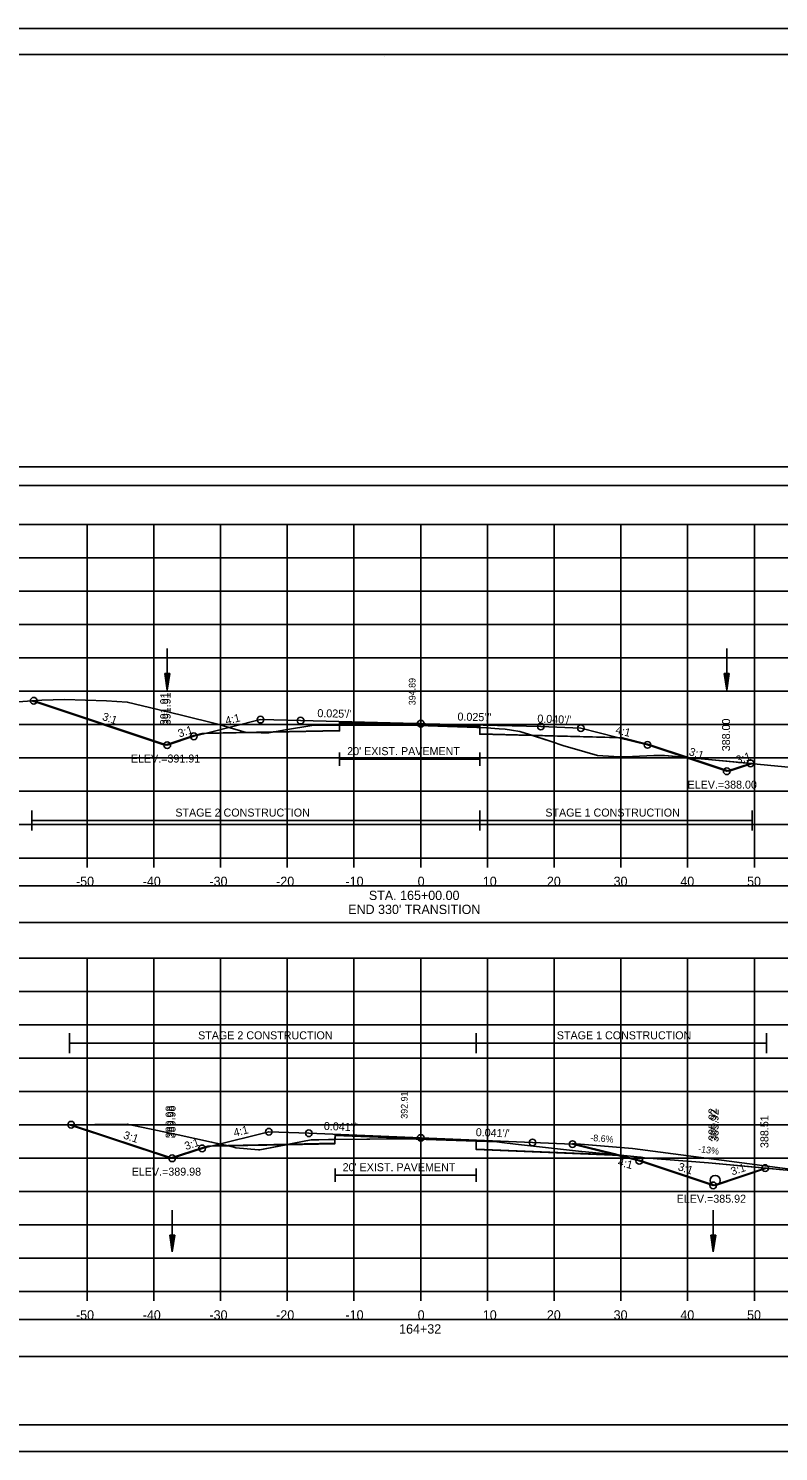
# Model space of a CAD drawing. Extents: x 1376273 to 1384221, y 378927 to 384592.
# Drawn here: x 1378165.7 to 1378278.1, y 380538.5 to 380751.8 of the extents above; entities that cross this region are included whole.
import ezdxf

# ---------------------------------------------------------------- set-up
doc = ezdxf.new("R2010")
doc.units = 0
for name, color, linetype in [('R_Alt Surface', 7, 'Continuous'), ('R_Axis', 7, 'Continuous'), ('R_Axis Annot', 7, 'Continuous'), ('R_Border', 7, 'Continuous'), ('R_Border Notes', 7, 'Continuous'), ('R_Contours', 7, 'Continuous'), ('R_Dimension', 7, 'Continuous'), ('R_Drive', 7, 'Continuous'), ('R_Exist Surface', 7, 'Continuous'), ('R_Fin Surface', 7, 'Continuous'), ('R_Grid', 7, 'Continuous'), ('R_No Plot', 7, 'Continuous'), ('R_Water', 7, 'Continuous'), ('R_Xsect Elev', 7, 'Continuous'), ('R_Xsect Slope', 7, 'Continuous'), ('T_Detection Zones', 7, 'Continuous'), ('T_Notes', 7, 'Continuous')]:
    doc.layers.add(name, color=color, linetype=linetype)

msp = doc.modelspace()

# ---------------------------------------------------------------- linework, layer by layer
at = {"layer": 'R_Alt Surface'}
for points in [[(1378192.36, 380646.2), (1378212.29, 380646.6), (1378212.3, 380647.77), (1378224.46, 380647.47), (1378233.31, 380647.25), (1378233.32, 380646.08), (1378253.97, 380645.57)], [(1378212.3, 380643.3), (1378212.3, 380641.3)], [(1378212.3, 380642.3), (1378233.31, 380642.3)], [(1378233.31, 380643.3), (1378233.31, 380641.3)], [(1378193.27, 380584.36), (1378211.61, 380584.72), (1378211.62, 380585.89), (1378224.46, 380585.37), (1378232.78, 380585.03), (1378232.79, 380583.86), (1378253.59, 380583.01)], [(1378211.62, 380580.93), (1378211.62, 380578.93)], [(1378211.62, 380579.93), (1378232.78, 380579.93)], [(1378232.78, 380580.93), (1378232.78, 380578.93)]]:
    msp.add_lwpolyline(points, dxfattribs=at)
at = {"layer": 'R_Axis'}
for p, q in [((1378074.46, 380627.49), (1378374.46, 380627.49)), ((1378174.46, 380626.09), (1378174.46, 380627.49)), ((1378184.46, 380626.09), (1378184.46, 380627.49)), ((1378194.46, 380626.09), (1378194.46, 380627.49)), ((1378204.46, 380626.09), (1378204.46, 380627.49)), ((1378214.46, 380626.09), (1378214.46, 380627.49)), ((1378224.46, 380626.09), (1378224.46, 380627.49)), ((1378234.46, 380626.09), (1378234.46, 380627.49)), ((1378244.46, 380626.09), (1378244.46, 380627.49)), ((1378254.46, 380626.09), (1378254.46, 380627.49)), ((1378264.46, 380626.09), (1378264.46, 380627.49)), ((1378274.46, 380626.09), (1378274.46, 380627.49)), ((1378074.46, 380562.49), (1378374.46, 380562.49)), ((1378174.46, 380561.09), (1378174.46, 380562.49)), ((1378184.46, 380561.09), (1378184.46, 380562.49)), ((1378194.46, 380561.09), (1378194.46, 380562.49)), ((1378204.46, 380561.09), (1378204.46, 380562.49)), ((1378214.46, 380561.09), (1378214.46, 380562.49)), ((1378224.46, 380561.09), (1378224.46, 380562.49)), ((1378234.46, 380561.09), (1378234.46, 380562.49)), ((1378244.46, 380561.09), (1378244.46, 380562.49)), ((1378254.46, 380561.09), (1378254.46, 380562.49)), ((1378264.46, 380561.09), (1378264.46, 380562.49)), ((1378274.46, 380561.09), (1378274.46, 380562.49))]:
    msp.add_line(p, q, dxfattribs=at)
at = {"layer": 'R_Axis Annot'}
for points in [[(1378072.9, 380683.32), (1378374.7, 380683.32), (1378374.7, 380686.14), (1378072.9, 380686.14)], [(1378073.48, 380617.81), (1378375.28, 380617.81), (1378375.28, 380623.33), (1378073.48, 380623.33)], [(1378073.48, 380552.76), (1378375.28, 380552.76), (1378375.28, 380558.29), (1378073.48, 380558.29)]]:
    msp.add_lwpolyline(points, close=True, dxfattribs=at)
at = {"layer": 'R_Border'}
for p, q in [((1378066.46, 380747.95), (1378382.64, 380747.95)), ((1378218.98, 380747.69), (1378218.98, 380747.69)), ((1378218.98, 380747.69), (1378218.98, 380747.69)), ((1378382.64, 380542.49), (1378066.46, 380542.49))]:
    msp.add_line(p, q, dxfattribs=at)
at = {"layer": 'R_Contours'}
for p, q in [((1378233.31, 380647.03), (1378233.32, 380646.03)), ((1378233.32, 380646.03), (1378241.25, 380645.84)), ((1378254.7, 380645.51), (1378241.25, 380645.84))]:
    msp.add_line(p, q, dxfattribs=at)
for points in [[(1378241.25, 380645.84), (1378239.3, 380646.47), (1378238.08, 380646.63), (1378237.14, 380646.78), (1378236.2, 380646.85), (1378234.31, 380646.99), (1378233.31, 380647.03)], [(1378241.25, 380645.84), (1378243.87, 380645), (1378245.92, 380644.33), (1378247.16, 380643.96), (1378250.93, 380642.87), (1378253.4, 380642.72), (1378254.51, 380642.66), (1378256.19, 380642.7), (1378259.4, 380642.88), (1378260.99, 380642.84), (1378264.54, 380642.54)], [(1378264.54, 380642.54), (1378258.95, 380644.41), (1378258.46, 380644.57), (1378254.7, 380645.51), (1378254.7, 380645.51)]]:
    msp.add_lwpolyline(points, dxfattribs=at)
for points in [[(1378264.54, 380642.54), (1378267.6, 380642.28), (1378274.15, 380641.65), (1378270.68, 380640.49)], [(1378232.78, 380585.06), (1378233.78, 380585.03), (1378234.39, 380585), (1378235.88, 380584.92), (1378236.61, 380584.82), (1378238.69, 380584.59), (1378248.12, 380583.54), (1378254.9, 380582.89), (1378257.4, 380582.64), (1378257.5, 380582.63), (1378258.02, 380582.56), (1378267.59, 380581.78), (1378276.3, 380580.98), (1378268.58, 380578.41), (1378257.22, 380582.2), (1378254.39, 380582.91), (1378232.79, 380583.79)]]:
    msp.add_lwpolyline(points, close=True, dxfattribs=at)
at = {"layer": 'R_Dimension'}
for p, q in [((1378166.16, 380631.6), (1378166.16, 380634.6)), ((1378166.16, 380633.1), (1378274.15, 380633.1)), ((1378233.31, 380631.6), (1378233.31, 380634.6)), ((1378274.15, 380631.6), (1378274.15, 380634.6)), ((1378171.81, 380598.21), (1378171.81, 380601.21)), ((1378232.78, 380598.21), (1378232.78, 380601.21)), ((1378276.3, 380598.21), (1378276.3, 380601.21)), ((1378171.81, 380599.71), (1378276.3, 380599.71))]:
    msp.add_line(p, q, dxfattribs=at)
at = {"layer": 'R_Drive'}
for p, q in [((1378247.22, 380584.7), (1378256.19, 380583.93)), ((1378256.19, 380583.93), (1378284.26, 380580.28))]:
    msp.add_line(p, q, dxfattribs=at)
at = {"layer": 'R_Exist Surface'}
for points in [[(1378164.11, 380650.91), (1378167.68, 380651.16), (1378171.07, 380651.25), (1378177.35, 380651.07), (1378180.49, 380650.87), (1378188.41, 380648.96), (1378194.24, 380647.52), (1378194.93, 380647.3), (1378198.32, 380646.29), (1378200.55, 380646.25), (1378201.68, 380646.25), (1378203.88, 380646.65), (1378208.42, 380647.4), (1378210.5, 380647.41), (1378211.3, 380647.42), (1378221.15, 380647.39), (1378223.38, 380647.39), (1378225.6, 380647.31), (1378234.31, 380646.99), (1378236.2, 380646.85), (1378237.14, 380646.78), (1378238.08, 380646.63), (1378239.3, 380646.47), (1378243.87, 380645), (1378245.92, 380644.33), (1378247.16, 380643.96), (1378250.93, 380642.87), (1378253.4, 380642.72), (1378254.51, 380642.66), (1378256.19, 380642.7), (1378259.4, 380642.88), (1378260.99, 380642.84), (1378267.6, 380642.28), (1378282.67, 380640.83)], [(1378164.26, 380587.43), (1378170.71, 380587.5), (1378180.49, 380587.6), (1378188.09, 380585.99), (1378193.13, 380584.9), (1378196.46, 380584.15), (1378196.76, 380584.06), (1378200.17, 380583.75), (1378200.36, 380583.75), (1378205.47, 380584.74), (1378208.04, 380585.22), (1378209.18, 380585.25), (1378210.62, 380585.29), (1378222.09, 380585.4), (1378222.19, 380585.4), (1378222.26, 380585.4), (1378233.78, 380585.03), (1378234.39, 380585), (1378235.88, 380584.92), (1378236.61, 380584.82), (1378238.69, 380584.59), (1378248.12, 380583.54), (1378254.9, 380582.89), (1378257.4, 380582.64), (1378257.5, 380582.63), (1378258.02, 380582.56), (1378267.59, 380581.78), (1378278.77, 380580.76)]]:
    msp.add_lwpolyline(points, dxfattribs=at)
at = {"layer": 'R_Fin Surface'}
for points in [[(1378166.46, 380651.07), (1378166.46, 380651.07), (1378167.26, 380650.81), (1378186.48, 380644.4), (1378190.46, 380645.73), (1378192.36, 380646.2), (1378192.36, 380646.2), (1378200.46, 380648.23), (1378206.46, 380648.08), (1378206.46, 380648.08), (1378223.74, 380647.65), (1378224.46, 380647.63), (1378225.18, 380647.62), (1378242.46, 380647.19), (1378242.46, 380647.19), (1378248.46, 380646.95), (1378253.97, 380645.57), (1378258.46, 380644.45), (1378258.93, 380644.29), (1378270.32, 380640.49), (1378270.32, 380640.49), (1378273.87, 380641.68)], [(1378172.08, 380587.51), (1378187.21, 380582.47), (1378191.69, 380583.96), (1378193.27, 380584.36), (1378201.69, 380586.46), (1378207.69, 380586.22), (1378224.46, 380585.53), (1378241.22, 380584.85), (1378247.22, 380584.6), (1378253.59, 380583.01), (1378257.22, 380582.1), (1378268.29, 380578.41), (1378276.07, 380581.01)]]:
    msp.add_lwpolyline(points, dxfattribs=at)
at = {"layer": 'R_Grid'}
for p, q in [((1378074.46, 380677.49), (1378374.46, 380677.49)), ((1378174.46, 380627.49), (1378174.46, 380677.49)), ((1378184.46, 380627.49), (1378184.46, 380677.49)), ((1378194.46, 380627.49), (1378194.46, 380677.49)), ((1378204.46, 380627.49), (1378204.46, 380677.49)), ((1378214.46, 380627.49), (1378214.46, 380677.49)), ((1378224.46, 380627.49), (1378224.46, 380677.49)), ((1378234.46, 380627.49), (1378234.46, 380677.49)), ((1378244.46, 380627.49), (1378244.46, 380677.49)), ((1378254.46, 380627.49), (1378254.46, 380677.49)), ((1378264.46, 380627.49), (1378264.46, 380677.49)), ((1378274.46, 380627.49), (1378274.46, 380677.49)), ((1378074.46, 380672.49), (1378374.46, 380672.49)), ((1378074.46, 380667.49), (1378374.46, 380667.49)), ((1378074.46, 380662.49), (1378374.46, 380662.49)), ((1378074.46, 380657.49), (1378374.46, 380657.49)), ((1378074.46, 380652.49), (1378374.46, 380652.49)), ((1378074.46, 380647.49), (1378374.46, 380647.49)), ((1378074.46, 380642.49), (1378374.46, 380642.49)), ((1378074.46, 380637.49), (1378374.46, 380637.49)), ((1378074.46, 380632.49), (1378374.46, 380632.49)), ((1378074.46, 380627.49), (1378374.46, 380627.49)), ((1378074.46, 380612.49), (1378374.46, 380612.49)), ((1378174.46, 380562.49), (1378174.46, 380612.49)), ((1378184.46, 380562.49), (1378184.46, 380612.49)), ((1378194.46, 380562.49), (1378194.46, 380612.49)), ((1378204.46, 380562.49), (1378204.46, 380612.49)), ((1378214.46, 380562.49), (1378214.46, 380612.49)), ((1378224.46, 380562.49), (1378224.46, 380612.49)), ((1378234.46, 380562.49), (1378234.46, 380612.49)), ((1378244.46, 380562.49), (1378244.46, 380612.49)), ((1378254.46, 380562.49), (1378254.46, 380612.49)), ((1378264.46, 380562.49), (1378264.46, 380612.49)), ((1378274.46, 380562.49), (1378274.46, 380612.49)), ((1378074.46, 380607.49), (1378374.46, 380607.49)), ((1378074.46, 380602.49), (1378374.46, 380602.49)), ((1378074.46, 380597.49), (1378374.46, 380597.49)), ((1378074.46, 380592.49), (1378374.46, 380592.49)), ((1378074.46, 380587.49), (1378374.46, 380587.49)), ((1378074.46, 380582.49), (1378374.46, 380582.49)), ((1378074.46, 380577.49), (1378374.46, 380577.49)), ((1378074.46, 380572.49), (1378374.46, 380572.49)), ((1378074.46, 380567.49), (1378374.46, 380567.49)), ((1378074.46, 380562.49), (1378374.46, 380562.49))]:
    msp.add_line(p, q, dxfattribs=at)
at = {"layer": 'R_No Plot'}
for p, q in [((1378054.06, 380751.85), (1378387.39, 380751.85)), ((1378054.06, 380538.52), (1378387.39, 380538.52))]:
    msp.add_line(p, q, dxfattribs=at)
for points in [[(1378054.05, 380751.85), (1378387.39, 380751.85), (1378387.39, 380538.51), (1378054.05, 380538.51)], [(1378300.38, 380747.95), (1378300.38, 380738.07), (1378336.11, 380738.07), (1378336.11, 380735.15), (1378359.31, 380735.15), (1378359.31, 380710.82), (1378382.64, 380710.82), (1378382.64, 380542.49), (1378066.46, 380542.49), (1378066.46, 380747.95)]]:
    msp.add_lwpolyline(points, close=True, dxfattribs=at)
for points in [[(1378191.64, 380646.14), (1378212.29, 380646.55), (1378212.3, 380647.89), (1378224.46, 380647.59), (1378233.31, 380647.37), (1378233.32, 380646.03), (1378254.7, 380645.51)], [(1378192.55, 380584.27), (1378211.61, 380584.65), (1378211.62, 380585.99), (1378224.46, 380585.46), (1378232.78, 380585.12), (1378232.79, 380583.79), (1378254.39, 380582.91)]]:
    msp.add_lwpolyline(points, dxfattribs=at)
for centre in [(1378166.46, 380651.07), (1378200.46, 380648.23), (1378206.46, 380648.08), (1378224.46, 380647.63), (1378242.46, 380647.19), (1378190.46, 380645.73), (1378248.46, 380646.95), (1378186.48, 380644.4), (1378186.48, 380644.4), (1378258.46, 380644.45), (1378273.87, 380641.68), (1378270.32, 380640.49), (1378270.32, 380640.49), (1378172.08, 380587.51), (1378201.69, 380586.46), (1378207.69, 380586.22), (1378224.46, 380585.53), (1378191.69, 380583.96), (1378241.22, 380584.85), (1378247.22, 380584.6), (1378187.21, 380582.47), (1378187.21, 380582.47), (1378257.22, 380582.1), (1378276.07, 380581.01), (1378268.29, 380578.41), (1378268.29, 380578.41)]:
    msp.add_circle(centre, 0.5, dxfattribs=at)
at = {"layer": 'R_Water'}
for p, q in [((1378186.48, 380658.88), (1378186.48, 380652.63)), ((1378270.32, 380658.88), (1378270.32, 380652.63)), ((1378186.1, 380655.13), (1378186.48, 380652.63)), ((1378186.85, 380655.13), (1378186.1, 380655.13)), ((1378186.17, 380655.13), (1378186.48, 380653.05)), ((1378186.23, 380655.13), (1378186.48, 380653.48)), ((1378186.29, 380655.13), (1378186.48, 380653.89)), ((1378186.36, 380655.13), (1378186.48, 380654.32)), ((1378186.42, 380655.13), (1378186.48, 380654.73)), ((1378186.85, 380655.13), (1378186.48, 380652.63)), ((1378186.6, 380655.13), (1378186.48, 380654.32)), ((1378186.73, 380655.13), (1378186.48, 380653.48)), ((1378186.79, 380655.13), (1378186.48, 380653.05)), ((1378186.66, 380655.13), (1378186.48, 380653.89)), ((1378186.54, 380655.13), (1378186.48, 380654.73)), ((1378269.95, 380655.13), (1378270.32, 380652.63)), ((1378270.7, 380655.13), (1378269.95, 380655.13)), ((1378270.01, 380655.13), (1378270.32, 380653.05)), ((1378270.07, 380655.13), (1378270.32, 380653.48)), ((1378270.13, 380655.13), (1378270.32, 380653.89)), ((1378270.2, 380655.13), (1378270.32, 380654.32)), ((1378270.26, 380655.13), (1378270.32, 380654.73)), ((1378270.7, 380655.13), (1378270.32, 380652.63)), ((1378270.44, 380655.13), (1378270.32, 380654.32)), ((1378270.57, 380655.13), (1378270.32, 380653.48)), ((1378270.63, 380655.13), (1378270.32, 380653.05)), ((1378270.51, 380655.13), (1378270.32, 380653.89)), ((1378270.38, 380655.13), (1378270.32, 380654.73)), ((1378187.21, 380574.68), (1378187.21, 380568.43)), ((1378268.29, 380574.68), (1378268.29, 380568.43)), ((1378186.84, 380570.93), (1378187.21, 380568.43)), ((1378187.59, 380570.93), (1378186.84, 380570.93)), ((1378186.9, 380570.93), (1378187.21, 380568.84)), ((1378186.96, 380570.93), (1378187.21, 380569.27)), ((1378187.03, 380570.93), (1378187.21, 380569.69)), ((1378187.09, 380570.93), (1378187.21, 380570.11)), ((1378187.15, 380570.93), (1378187.21, 380570.53)), ((1378187.59, 380570.93), (1378187.21, 380568.43)), ((1378187.33, 380570.93), (1378187.21, 380570.11)), ((1378187.46, 380570.93), (1378187.21, 380569.27)), ((1378187.52, 380570.93), (1378187.21, 380568.84)), ((1378187.4, 380570.93), (1378187.21, 380569.69)), ((1378187.27, 380570.93), (1378187.21, 380570.53)), ((1378267.92, 380570.93), (1378268.29, 380568.43)), ((1378268.67, 380570.93), (1378267.92, 380570.93)), ((1378267.98, 380570.93), (1378268.29, 380568.84)), ((1378268.04, 380570.93), (1378268.29, 380569.27)), ((1378268.11, 380570.93), (1378268.29, 380569.69)), ((1378268.17, 380570.93), (1378268.29, 380570.11)), ((1378268.23, 380570.93), (1378268.29, 380570.53)), ((1378268.67, 380570.93), (1378268.29, 380568.43)), ((1378268.41, 380570.93), (1378268.29, 380570.11)), ((1378268.54, 380570.93), (1378268.29, 380569.27)), ((1378268.6, 380570.93), (1378268.29, 380568.84)), ((1378268.48, 380570.93), (1378268.29, 380569.69)), ((1378268.35, 380570.93), (1378268.29, 380570.53))]:
    msp.add_line(p, q, dxfattribs=at)
msp.add_circle((1378268.59, 380579.16), 0.75, dxfattribs=at)
at = {"layer": 'T_Detection Zones'}
for p, q in [((1378191.64, 380646.14), (1378198.69, 380646.28)), ((1378202.25, 380646.35), (1378198.69, 380646.28)), ((1378202.25, 380646.35), (1378212.29, 380646.55)), ((1378212.29, 380646.55), (1378212.29, 380647.42)), ((1378233.31, 380647.03), (1378233.31, 380647.37))]:
    msp.add_line(p, q, dxfattribs=at)
for points in [[(1378198.69, 380646.28), (1378198.32, 380646.29), (1378195.54, 380647.12), (1378194.93, 380647.3), (1378194.24, 380647.52), (1378188.41, 380648.96), (1378180.49, 380650.87), (1378177.35, 380651.07), (1378171.07, 380651.25), (1378167.68, 380651.16), (1378166.16, 380651.05)], [(1378166.16, 380651.05), (1378166.96, 380650.79), (1378186.12, 380644.4), (1378190.46, 380645.85), (1378191.64, 380646.14)], [(1378233.31, 380647.37), (1378224.46, 380647.59), (1378212.3, 380647.89), (1378212.29, 380647.42)], [(1378191.64, 380646.14), (1378191.64, 380646.14)], [(1378198.69, 380646.28), (1378200.55, 380646.25), (1378201.68, 380646.25), (1378202.25, 380646.35)], [(1378212.29, 380647.42), (1378211.3, 380647.42), (1378210.5, 380647.41), (1378208.42, 380647.4), (1378203.88, 380646.65), (1378202.25, 380646.35)], [(1378212.29, 380647.42), (1378221.15, 380647.39), (1378223.38, 380647.39), (1378225.6, 380647.31), (1378233.31, 380647.03)]]:
    msp.add_lwpolyline(points, dxfattribs=at)
for points in [[(1378171.81, 380587.51), (1378180.49, 380587.6), (1378188.09, 380585.99), (1378193.13, 380584.9), (1378195.64, 380584.33), (1378192.55, 380584.27), (1378191.69, 380584.06), (1378186.93, 380582.47)], [(1378211.61, 380585.3), (1378222.09, 380585.4), (1378222.19, 380585.4), (1378222.26, 380585.4), (1378232.78, 380585.06), (1378232.78, 380585.12), (1378224.46, 380585.46), (1378211.62, 380585.99)], [(1378195.64, 380584.33), (1378196.46, 380584.15), (1378196.76, 380584.06), (1378200.17, 380583.75), (1378200.36, 380583.75), (1378204.28, 380584.51)], [(1378204.28, 380584.51), (1378205.47, 380584.74), (1378208.04, 380585.22), (1378209.18, 380585.25), (1378210.62, 380585.29), (1378211.61, 380585.3), (1378211.61, 380584.65)]]:
    msp.add_lwpolyline(points, close=True, dxfattribs=at)
at = {"layer": 'T_Notes'}
for p, q in [((1378256.19, 380583.93), (1378247.22, 380584.7)), ((1378284.26, 380580.28), (1378256.19, 380583.93))]:
    msp.add_line(p, q, dxfattribs=at)
for points in [[(1378247.22, 380584.7), (1378253.53, 380583.12), (1378254.18, 380582.96), (1378257.22, 380582.2)], [(1378257.22, 380582.2), (1378268.58, 380578.41), (1378276.3, 380580.98)], [(1378276.3, 380580.98), (1378278.77, 380580.76), (1378284.26, 380580.28)]]:
    msp.add_lwpolyline(points, dxfattribs=at)

# ---------------------------------------------------------------- texts
at = {"layer": 'R_Alt Surface'}
for p in [(1378213.44, 380642.91), (1378212.76, 380580.54)]:
    msp.add_text("20' EXIST. PAVEMENT", height=1.2, dxfattribs=at).set_placement(p)
at = {"layer": 'R_Axis Annot'}
for s, p in [('-50', (1378172.8, 380623.29)), ('-40', (1378182.8, 380623.29)), ('-30', (1378192.8, 380623.29)), ('-20', (1378202.8, 380623.29)), ('-10', (1378213.19, 380623.29)), ('0', (1378224, 380623.29)), ('10', (1378233.77, 380623.29)), ('20', (1378243.37, 380623.29)), ('30', (1378253.37, 380623.29)), ('40', (1378263.37, 380623.29)), ('50', (1378273.37, 380623.29)), ('STA. 165+00.00', (1378216.69, 380621.19)), ("END 330' TRANSITION", (1378213.6, 380619.09)), ('-50', (1378172.8, 380558.29)), ('-40', (1378182.8, 380558.29)), ('-30', (1378192.8, 380558.29)), ('-20', (1378202.8, 380558.29)), ('-10', (1378213.19, 380558.29)), ('0', (1378224, 380558.29)), ('10', (1378233.77, 380558.29)), ('20', (1378243.37, 380558.29)), ('30', (1378253.37, 380558.29)), ('40', (1378263.37, 380558.29)), ('50', (1378273.37, 380558.29)), ('164+32', (1378221.23, 380556.19))]:
    msp.add_text(s, height=1.4, dxfattribs=at).set_placement(p)
at = {"layer": 'R_Border Notes'}
for s, p in [('ELEV.=391.91', (1378181.02, 380641.8)), ('ELEV.=388.00', (1378264.45, 380637.89)), ('ELEV.=389.98', (1378181.15, 380579.87)), ('ELEV.=385.92', (1378262.82, 380575.81))]:
    msp.add_text(s, height=1.2, dxfattribs=at).set_placement(p)
at = {"layer": 'R_Dimension'}
for s, p in [('STAGE 2 CONSTRUCTION', (1378187.69, 380633.7)), ('STAGE 1 CONSTRUCTION', (1378243.14, 380633.7)), ('STAGE 2 CONSTRUCTION', (1378191.1, 380600.31)), ('STAGE 1 CONSTRUCTION', (1378244.86, 380600.31))]:
    msp.add_text(s, height=1.2, dxfattribs=at).set_placement(p)
at = {"layer": 'R_Drive'}
for s, rotation, p in [('-8.6%', 355.0754, (1378249.84, 380585.09)), ('-13%', 352.5898, (1378266, 380583.41))]:
    msp.add_text(s, height=1, rotation=rotation, dxfattribs=at).set_placement(p)
at = {"layer": 'R_No Plot'}
for s, p in [('391.91', (1378186.62, 380647.4)), ('388.00', (1378270.82, 380643.49)), ('389.98', (1378187.43, 380585.47)), ('385.92', (1378269.09, 380584.92))]:
    msp.add_text(s, height=1.2, rotation=90, dxfattribs=at).set_placement(p)
at = {"layer": 'R_Xsect Elev'}
for s, height, p in [('394.89', 1, (1378223.68, 380650.39)), ('391.91', 1.2, (1378186.98, 380647.4)), ('388.00', 1.2, (1378270.82, 380643.49)), ('392.91', 1, (1378222.49, 380588.4)), ('389.98', 1.2, (1378187.71, 380585.47)), ('385.92', 1.2, (1378268.79, 380585.09)), ('388.51', 1.2, (1378276.57, 380584.01))]:
    msp.add_text(s, height=height, rotation=90, dxfattribs=at).set_placement(p)
at = {"layer": 'R_Xsect Slope'}
for s, rotation, p in [("0.025'/'", 358.5852, (1378208.96, 380648.62)), ('3:1', 341.5651, (1378176.63, 380648.21)), ('4:1', 14.0362, (1378195.34, 380647.46)), ("0.025'/'", 358.5852, (1378229.96, 380648.1)), ("0.040'/'", 357.7094, (1378241.92, 380647.81)), ('3:1', 18.4349, (1378188.31, 380645.54)), ('4:1', 345.9638, (1378253.58, 380646.18)), ('3:1', 341.5651, (1378264.55, 380642.95)), ('3:1', 18.4349, (1378271.94, 380641.56)), ("0.041'/'", 357.6586, (1378209.93, 380586.73)), ('3:1', 341.5651, (1378179.81, 380585.47)), ('4:1', 14.0362, (1378196.57, 380585.7)), ("0.041'/'", 357.6586, (1378232.69, 380585.8)), ('3:1', 18.4349, (1378189.29, 380583.69)), ('4:1', 345.9638, (1378253.9, 380581.39)), ('3:1', 341.5651, (1378262.91, 380580.73)), ('3:1', 18.4349, (1378271.15, 380579.89))]:
    msp.add_text(s, height=1.2, rotation=rotation, dxfattribs=at).set_placement(p)

doc.saveas('drawing.dxf')
